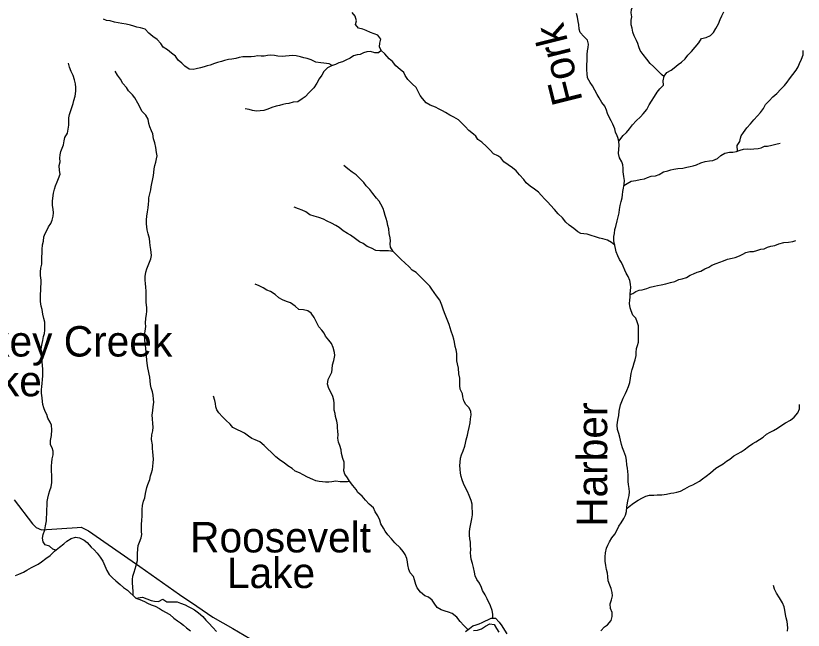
# Model space of a CAD drawing. Extents: x 1624196 to 2029251, y 146837 to 440034.
# Drawn here: x 1772378 to 1785324, y 265741 to 275842 of the extents above; entities that cross this region are included whole.
import ezdxf

# ---------------------------------------------------------------- set-up
doc = ezdxf.new("R2010")
doc.units = 0
for name, color, linetype in [('GM_X_Major_River', 7, 'Continuous'), ('GM_X_Minor_Lake', 7, 'Continuous'), ('GM_X_Minor_Lake_Text', 7, 'Continuous'), ('GM_X_Minor_River', 7, 'Continuous'), ('GM_X_Minor_River_Text', 7, 'Continuous'), ('GM_X_State_Route', 7, 'Continuous')]:
    doc.layers.add(name, color=color, linetype=linetype)

msp = doc.modelspace()

# ---------------------------------------------------------------- linework, layer by layer
at = {"layer": 'GM_X_Major_River'}
for points in [[(1772376, 266640), (1772430, 266662), (1772506, 266698), (1772560, 266728), (1772635, 266773), (1772691, 266799), (1772745, 266829), (1772803, 266865), (1772873, 266920), (1772944, 266972), (1773016, 267040), (1773098, 267107), (1773168, 267163), (1773220, 267207), (1773289, 267250), (1773359, 267270), (1773427, 267262), (1773500, 267222), (1773550, 267184), (1773616, 267106), (1773667, 267062), (1773715, 267006), (1773765, 266944), (1773812, 266876), (1773844, 266800), (1773874, 266725), (1773912, 266657), (1773971, 266601), (1774025, 266551), (1774096, 266493), (1774150, 266443), (1774214, 266397), (1774353, 266269)], [(1779772, 265721), (1779836, 265772), (1779894, 265816), (1779945, 265830), (1779997, 265846), (1780047, 265870), (1780196, 265939)], [(1780196, 265939), (1780264, 265937), (1780324, 265875), (1780371, 265811), (1780415, 265743), (1780451, 265681)], [(1779903, 265736), (1779969, 265742), (1780035, 265764), (1780099, 265810), (1780170, 265845), (1780240, 265837), (1780280, 265769), (1780317, 265710)]]:
    msp.add_lwpolyline(points, dxfattribs=at)
at = {"layer": 'GM_X_Minor_Lake'}
for points in [[(1774353, 266269), (1774462, 266287), (1774530, 266257), (1774604, 266232), (1774659, 266220), (1774727, 266216), (1774793, 266254), (1774859, 266208), (1774910, 266206), (1774980, 266208), (1775034, 266210), (1775088, 266188), (1775163, 266159), (1775213, 266131), (1775265, 266103), (1775316, 266075), (1775380, 266027), (1775454, 265967), (1775501, 265907), (1775551, 265857), (1775615, 265788), (1775676, 265718)], [(1774353, 266269), (1774419, 266247), (1774494, 266213), (1774544, 266187), (1774602, 266157), (1774667, 266135), (1774741, 266097), (1774791, 266065), (1774842, 266040), (1774910, 266000), (1774978, 265940), (1775035, 265896), (1775085, 265862), (1775135, 265822), (1775186, 265779), (1775250, 265729)]]:
    msp.add_lwpolyline(points, dxfattribs=at)
at = {"layer": 'GM_X_Minor_River'}
for points in [[(1783036, 274837), (1782991, 274878), (1782931, 274936), (1782863, 275005), (1782808, 275059), (1782750, 275126), (1782691, 275203), (1782641, 275273), (1782619, 275333), (1782602, 275384), (1782582, 275434), (1782542, 275510), (1782523, 275571), (1782509, 275639), (1782496, 275691), (1782494, 275769), (1782504, 275825), (1782497, 275888), (1782499, 275942), (1782522, 276000), (1782536, 276050)], [(1779939, 273861), (1779901, 273897), (1779827, 273955), (1779768, 274024), (1779712, 274076), (1779654, 274133), (1779582, 274174), (1779512, 274210), (1779443, 274251), (1779391, 274277), (1779337, 274305), (1779277, 274340), (1779191, 274371), (1779127, 274409), (1779066, 274482), (1779028, 274532), (1778995, 274598), (1778959, 274665), (1778893, 274725), (1778826, 274796), (1778782, 274859), (1778756, 274909), (1778695, 274961), (1778625, 275020), (1778571, 275089), (1778518, 275135), (1778444, 275214), (1778386, 275270), (1778355, 275331), (1778361, 275389), (1778382, 275455), (1778330, 275523), (1778210, 275568), (1778140, 275599), (1778084, 275621), (1778010, 275640), (1777963, 275698), (1777977, 275758), (1777958, 275835), (1777908, 275893)], [(1782290, 273781), (1782365, 273873), (1782418, 273923), (1782468, 273983), (1782517, 274050), (1782577, 274112), (1782646, 274178), (1782692, 274232), (1782751, 274300), (1782789, 274376), (1782830, 274440), (1782876, 274513), (1782925, 274583), (1782967, 274641), (1783026, 274701), (1783020, 274773), (1783039, 274847), (1783081, 274907), (1783153, 274945), (1783204, 274987), (1783268, 275040), (1783322, 275080), (1783385, 275136), (1783429, 275192), (1783488, 275254), (1783548, 275327), (1783609, 275397), (1783649, 275467), (1783726, 275483), (1783798, 275516), (1783846, 275568), (1783885, 275634), (1783929, 275708), (1783958, 275778), (1783984, 275838), (1784021, 275908)], [(1777578, 275024), (1777528, 275051), (1777444, 275062), (1777392, 275068), (1777310, 275081), (1777232, 275115), (1777168, 275138), (1777116, 275148), (1777060, 275166), (1776986, 275185), (1776922, 275189), (1776872, 275182), (1776810, 275176), (1776756, 275174), (1776684, 275179), (1776630, 275187), (1776572, 275196), (1776518, 275190), (1776462, 275180), (1776410, 275179), (1776352, 275181), (1776301, 275173), (1776247, 275168), (1776195, 275168), (1776113, 275164), (1776049, 275155), (1775995, 275141), (1775929, 275129), (1775877, 275122), (1775808, 275108), (1775758, 275092), (1775694, 275075), (1775644, 275055), (1775576, 275027), (1775526, 275018), (1775473, 275004), (1775417, 274986), (1775345, 274971), (1775293, 274961), (1775229, 274965), (1775155, 275014), (1775107, 275065), (1775048, 275113), (1775006, 275175), (1774936, 275226), (1774873, 275279), (1774803, 275327), (1774761, 275384), (1774701, 275452), (1774632, 275503), (1774568, 275557), (1774506, 275620), (1774428, 275642), (1774370, 275653), (1774319, 275669), (1774263, 275686), (1774191, 275704), (1774123, 275717), (1774061, 275727), (1773999, 275739), (1773929, 275756), (1773871, 275762), (1773819, 275785)], [(1782277, 273843), (1782263, 273868), (1782240, 273930), (1782226, 273982), (1782192, 274059), (1782167, 274115), (1782139, 274165), (1782107, 274236), (1782088, 274288), (1782062, 274354), (1782011, 274417), (1781971, 274491), (1781937, 274550), (1781900, 274620), (1781858, 274690), (1781819, 274743), (1781775, 274821), (1781771, 274892), (1781766, 274948), (1781768, 275010), (1781769, 275136), (1781774, 275204), (1781778, 275263), (1781786, 275321), (1781795, 275373), (1781777, 275443), (1781717, 275500), (1781658, 275566), (1781640, 275622), (1781635, 275699), (1781625, 275749), (1781613, 275817), (1781598, 275877)], [(1778387, 275269), (1778340, 275234), (1778280, 275235), (1778208, 275253), (1778148, 275250), (1778092, 275232), (1778042, 275206), (1777989, 275197), (1777931, 275183), (1777873, 275145), (1777803, 275110), (1777752, 275086), (1777688, 275066), (1777632, 275042), (1777568, 275021), (1777501, 274983), (1777445, 274923), (1777409, 274865), (1777368, 274803), (1777328, 274733), (1777279, 274658), (1777204, 274580), (1777138, 274510), (1777088, 274474), (1777013, 274427), (1776937, 274423), (1776867, 274402), (1776817, 274394), (1776767, 274384), (1776712, 274366), (1776660, 274353), (1776588, 274331), (1776524, 274305), (1776454, 274286), (1776394, 274280), (1776337, 274275), (1776271, 274283), (1776217, 274299), (1776148, 274312)], [(1784293, 273828), (1784301, 273869), (1784344, 273922), (1784394, 273998), (1784455, 274066), (1784513, 274130), (1784572, 274196), (1784622, 274252), (1784671, 274315), (1784705, 274385), (1784766, 274443), (1784826, 274507), (1784889, 274565), (1784957, 274636), (1785018, 274696), (1785062, 274750), (1785100, 274804), (1785155, 274874), (1785208, 274950), (1785238, 275004), (1785262, 275058), (1785295, 275126), (1785321, 275200), (1785324, 275270)], [(1773230, 273912), (1773242, 273975), (1773252, 274041), (1773249, 274100), (1773249, 274164), (1773262, 274218), (1773276, 274268), (1773298, 274334), (1773321, 274398), (1773333, 274448), (1773352, 274520), (1773366, 274600), (1773367, 274662), (1773359, 274723), (1773346, 274789), (1773322, 274861), (1773288, 274928), (1773261, 274996), (1773247, 275060)], [(1774631, 273901), (1774609, 273951), (1774580, 274017), (1774568, 274073), (1774557, 274143), (1774515, 274210), (1774451, 274274), (1774418, 274343), (1774384, 274407), (1774337, 274494), (1774299, 274544), (1774233, 274607), (1774196, 274663), (1774136, 274728), (1774098, 274802), (1774051, 274867), (1774011, 274933)], [(1773108, 273238), (1773095, 273300), (1773093, 273382), (1773108, 273442), (1773104, 273500), (1773106, 273555), (1773121, 273613), (1773143, 273665), (1773160, 273719), (1773174, 273785), (1773186, 273839), (1773230, 273912)], [(1774544, 272616), (1774552, 272684), (1774561, 272744), (1774563, 272797), (1774567, 272851), (1774582, 272913), (1774596, 272979), (1774604, 273031), (1774617, 273083), (1774627, 273133), (1774642, 273217), (1774648, 273267), (1774655, 273323), (1774665, 273381), (1774683, 273435), (1774694, 273488), (1774700, 273540), (1774694, 273596), (1774681, 273676), (1774663, 273752), (1774642, 273819), (1774631, 273901)], [(1782226, 272073), (1782172, 272116), (1782106, 272152), (1782030, 272175), (1781977, 272187), (1781909, 272206), (1781839, 272232), (1781773, 272250), (1781719, 272259), (1781669, 272265), (1781617, 272291), (1781551, 272344), (1781473, 272398), (1781423, 272451), (1781365, 272521), (1781296, 272586), (1781232, 272655), (1781170, 272727), (1781126, 272777), (1781078, 272828), (1781014, 272892), (1780971, 272943), (1780907, 272991), (1780837, 273038), (1780767, 273096), (1780731, 273151), (1780661, 273225), (1780605, 273292), (1780542, 273344), (1780472, 273389), (1780404, 273443), (1780354, 273504), (1780302, 273538), (1780234, 273570), (1780178, 273631), (1780116, 273693), (1780042, 273762), (1779976, 273807), (1779939, 273861)], [(1782481, 271268), (1782486, 271324), (1782488, 271374), (1782483, 271430), (1782471, 271491), (1782443, 271557), (1782413, 271609), (1782392, 271659), (1782364, 271724), (1782336, 271784), (1782302, 271836), (1782275, 271895), (1782251, 271963), (1782237, 272015), (1782228, 272065), (1782212, 272140), (1782208, 272212), (1782219, 272262), (1782227, 272328), (1782242, 272380), (1782262, 272470), (1782283, 272536), (1782295, 272602), (1782304, 272656), (1782312, 272723), (1782328, 272787), (1782345, 272849), (1782353, 272899), (1782360, 272955), (1782370, 273005), (1782380, 273073), (1782387, 273131), (1782377, 273199), (1782364, 273274), (1782364, 273336), (1782360, 273390), (1782343, 273440), (1782301, 273505), (1782285, 273577), (1782292, 273647), (1782300, 273711), (1782290, 273781), (1782277, 273843)], [(1784243, 273617), (1784237, 273710), (1784279, 273776), (1784293, 273828)], [(1782377, 273049), (1782429, 273087), (1782497, 273125), (1782569, 273134), (1782642, 273152), (1782712, 273161), (1782764, 273183), (1782821, 273203), (1782895, 273212), (1782957, 273232), (1783024, 273274), (1783098, 273294), (1783149, 273309), (1783199, 273321), (1783263, 273329), (1783343, 273336), (1783408, 273352), (1783464, 273364), (1783516, 273375), (1783567, 273391), (1783639, 273423), (1783711, 273444), (1783784, 273456), (1783840, 273460), (1783916, 273495), (1783967, 273547), (1784037, 273581), (1784112, 273599), (1784166, 273602), (1784228, 273612), (1784289, 273634), (1784341, 273647), (1784405, 273653), (1784459, 273649), (1784514, 273652), (1784580, 273662), (1784630, 273672), (1784686, 273698), (1784737, 273699), (1784805, 273713), (1784873, 273729), (1784942, 273750)], [(1778533, 272090), (1778541, 272140), (1778531, 272191), (1778516, 272265), (1778512, 272337), (1778496, 272395), (1778483, 272454), (1778467, 272510), (1778453, 272560), (1778432, 272616), (1778416, 272676), (1778382, 272743), (1778350, 272793), (1778309, 272844), (1778249, 272918), (1778197, 272985), (1778139, 273047), (1778099, 273101), (1778032, 273168), (1777972, 273226), (1777906, 273269), (1777838, 273323), (1777774, 273378)], [(1773039, 267059), (1772988, 267075), (1772932, 267121), (1772864, 267144), (1772826, 267196), (1772816, 267256), (1772827, 267314), (1772855, 267392), (1772868, 267457), (1772882, 267537), (1772886, 267589), (1772891, 267655), (1772891, 267727), (1772894, 267793), (1772894, 267857), (1772905, 267914), (1772921, 267982), (1772937, 268036), (1772958, 268100), (1772970, 268170), (1772973, 268220), (1772969, 268290), (1772968, 268358), (1772968, 268442), (1772970, 268501), (1772979, 268559), (1772991, 268623), (1772992, 268685), (1772976, 268737), (1772948, 268789), (1772951, 268858), (1772965, 268942), (1772972, 269036), (1772964, 269110), (1772942, 269160), (1772905, 269229), (1772887, 269285), (1772863, 269339), (1772840, 269396), (1772822, 269450), (1772820, 269500), (1772810, 269560), (1772801, 269636), (1772799, 269695), (1772804, 269745), (1772814, 269797), (1772816, 269865), (1772823, 269923), (1772825, 269977), (1772823, 270027), (1772816, 270098), (1772810, 270150), (1772808, 270204), (1772805, 270262), (1772801, 270312), (1772797, 270366), (1772812, 270452), (1772824, 270506), (1772833, 270569), (1772849, 270619), (1772858, 270671), (1772858, 270749), (1772854, 270805), (1772837, 270865), (1772823, 270934), (1772814, 271014), (1772796, 271070), (1772784, 271146), (1772783, 271198), (1772787, 271261), (1772789, 271333), (1772792, 271383), (1772794, 271443), (1772796, 271497), (1772787, 271571), (1772785, 271634), (1772792, 271690), (1772804, 271760), (1772809, 271820), (1772810, 272000), (1772820, 272076), (1772833, 272139), (1772841, 272205), (1772859, 272261), (1772888, 272313), (1772916, 272371), (1772953, 272425), (1772979, 272481), (1772994, 272547), (1772996, 272603), (1772992, 272665), (1772983, 272723), (1772983, 272795), (1772986, 272845), (1772998, 272924), (1773013, 272992), (1773029, 273044), (1773059, 273110), (1773080, 273164), (1773108, 273238)], [(1778580, 271968), (1778508, 271978), (1778432, 271975), (1778361, 271975), (1778297, 271983), (1778225, 272020), (1778153, 272048), (1778089, 272097), (1778029, 272125), (1777965, 272174), (1777883, 272234), (1777833, 272261), (1777763, 272309), (1777693, 272360), (1777639, 272394), (1777569, 272431), (1777499, 272467), (1777435, 272500), (1777361, 272526), (1777285, 272547), (1777215, 272569), (1777147, 272620), (1777089, 272648), (1777025, 272668), (1776953, 272695)], [(1774309, 266310), (1774308, 266376), (1774302, 266450), (1774297, 266522), (1774295, 266576), (1774300, 266628), (1774322, 266697), (1774342, 266749), (1774359, 266805), (1774377, 266889), (1774378, 267005), (1774383, 267075), (1774391, 267133), (1774411, 267189), (1774438, 267259), (1774448, 267313), (1774447, 267366), (1774445, 267416), (1774447, 267480), (1774452, 267548), (1774454, 267616), (1774457, 267668), (1774457, 267724), (1774461, 267791), (1774480, 267861), (1774498, 267915), (1774513, 267987), (1774523, 268037), (1774533, 268089), (1774550, 268139), (1774580, 268219), (1774595, 268281), (1774607, 268331), (1774626, 268385), (1774634, 268439), (1774638, 268495), (1774641, 268551), (1774639, 268614), (1774633, 268674), (1774628, 268726), (1774626, 268790), (1774611, 268874), (1774617, 268955), (1774632, 269017), (1774638, 269077), (1774634, 269141), (1774627, 269215), (1774623, 269277), (1774630, 269351), (1774636, 269414), (1774647, 269488), (1774645, 269540), (1774639, 269606), (1774624, 269662), (1774602, 269723), (1774594, 269779), (1774583, 269903), (1774573, 269953), (1774561, 270004), (1774550, 270056), (1774536, 270130), (1774530, 270182), (1774527, 270250), (1774519, 270300), (1774514, 270383), (1774506, 270451), (1774502, 270521), (1774495, 270593), (1774505, 270659), (1774514, 270732), (1774510, 270786), (1774517, 270872), (1774527, 270932), (1774534, 270986), (1774530, 271046), (1774524, 271127), (1774519, 271191), (1774519, 271241), (1774524, 271313), (1774518, 271381), (1774512, 271439), (1774507, 271496), (1774507, 271558), (1774515, 271626), (1774532, 271680), (1774552, 271734), (1774577, 271792), (1774599, 271848), (1774607, 271900), (1774606, 271952), (1774600, 272002), (1774590, 272065), (1774581, 272121), (1774577, 272181), (1774554, 272259), (1774540, 272321), (1774532, 272372), (1774528, 272424), (1774525, 272486), (1774531, 272546), (1774544, 272616)], [(1782481, 271260), (1782520, 271276), (1782574, 271310), (1782624, 271329), (1782677, 271337), (1782753, 271361), (1782805, 271380), (1782878, 271398), (1782930, 271410), (1782986, 271419), (1783063, 271433), (1783141, 271457), (1783215, 271472), (1783276, 271504), (1783334, 271520), (1783404, 271537), (1783467, 271575), (1783519, 271601), (1783582, 271629), (1783640, 271644), (1783704, 271682), (1783769, 271710), (1783819, 271740), (1783894, 271771), (1783954, 271791), (1784014, 271813), (1784079, 271838), (1784153, 271856), (1784203, 271866), (1784278, 271893), (1784330, 271925), (1784380, 271951), (1784443, 271967), (1784505, 271968), (1784559, 271982), (1784628, 272004), (1784680, 272011), (1784738, 272037), (1784789, 272057), (1784859, 272064), (1784925, 272094), (1785002, 272112), (1785080, 272119), (1785150, 272129), (1785201, 272145)], [(1780224, 265938), (1780220, 265943), (1780219, 266004), (1780209, 266066), (1780181, 266142), (1780130, 266255), (1780092, 266325), (1780051, 266396), (1780033, 266446), (1780001, 266514), (1779955, 266577), (1779932, 266635), (1779922, 266695), (1779904, 266771), (1779885, 266838), (1779865, 266908), (1779857, 266958), (1779852, 267014), (1779858, 267068), (1779854, 267136), (1779851, 267187), (1779845, 267243), (1779839, 267305), (1779838, 267359), (1779842, 267409), (1779852, 267461), (1779865, 267515), (1779875, 267573), (1779884, 267640), (1779884, 267692), (1779882, 267746), (1779879, 267814), (1779865, 267872), (1779831, 267955), (1779806, 268021), (1779764, 268093), (1779738, 268154), (1779719, 268212), (1779701, 268270), (1779691, 268322), (1779682, 268387), (1779680, 268449), (1779682, 268501), (1779691, 268569), (1779703, 268625), (1779734, 268691), (1779758, 268765), (1779769, 268817), (1779783, 268869), (1779804, 268949), (1779816, 269003), (1779830, 269073), (1779847, 269148), (1779855, 269214), (1779864, 269284), (1779860, 269338), (1779834, 269396), (1779775, 269453), (1779745, 269511), (1779729, 269575), (1779720, 269629), (1779684, 269704), (1779678, 269762), (1779679, 269818), (1779677, 269882), (1779663, 269957), (1779656, 270051), (1779640, 270119), (1779631, 270169), (1779629, 270226), (1779627, 270290), (1779620, 270348), (1779604, 270404), (1779588, 270474), (1779579, 270527), (1779563, 270581), (1779535, 270659), (1779518, 270713), (1779502, 270766), (1779482, 270824), (1779446, 270906), (1779425, 270958), (1779405, 271021), (1779381, 271085), (1779348, 271165), (1779296, 271236), (1779256, 271292), (1779218, 271345), (1779187, 271395), (1779133, 271451), (1779081, 271500), (1779033, 271552), (1778961, 271619), (1778895, 271661), (1778843, 271712), (1778772, 271782), (1778714, 271835), (1778648, 271899), (1778580, 271968), (1778536, 272038), (1778533, 272090)], [(1776379, 271403), (1776315, 271431)], [(1779814, 265754), (1779806, 265759), (1779746, 265818), (1779684, 265886), (1779630, 265955), (1779552, 266015), (1779494, 266038), (1779438, 266056), (1779370, 266077), (1779306, 266117), (1779254, 266184), (1779223, 266236), (1779161, 266286), (1779103, 266309), (1779031, 266365), (1778977, 266438), (1778955, 266494), (1778932, 266570), (1778916, 266623), (1778862, 266685), (1778840, 266737), (1778821, 266814), (1778817, 266864), (1778805, 266918), (1778778, 266986), (1778746, 267037), (1778700, 267097), (1778610, 267176), (1778557, 267242), (1778493, 267307), (1778453, 267367), (1778421, 267417), (1778377, 267490), (1778362, 267550), (1778328, 267620), (1778286, 267685), (1778257, 267755), (1778187, 267814), (1778129, 267880), (1778071, 267943), (1778001, 268003), (1777974, 268055), (1777918, 268120), (1777862, 268194), (1777830, 268245), (1777788, 268305), (1777773, 268361), (1777777, 268431), (1777778, 268504), (1777754, 268566), (1777732, 268646), (1777725, 268704), (1777707, 268777), (1777685, 268833), (1777672, 268899), (1777676, 268953), (1777674, 269016), (1777667, 269070), (1777665, 269120), (1777657, 269178), (1777636, 269252), (1777630, 269306), (1777614, 269361), (1777611, 269413), (1777611, 269471), (1777605, 269523), (1777590, 269583), (1777556, 269654), (1777526, 269712), (1777501, 269784), (1777513, 269861), (1777544, 269931), (1777572, 269983), (1777582, 270033), (1777585, 270101), (1777605, 270175), (1777622, 270255), (1777620, 270309), (1777595, 270391), (1777569, 270456), (1777525, 270508), (1777469, 270575), (1777448, 270625), (1777412, 270675), (1777360, 270730), (1777324, 270804), (1777285, 270882), (1777233, 270951), (1777177, 270989), (1777109, 271006), (1777033, 271012), (1776969, 271067), (1776895, 271121), (1776827, 271144), (1776761, 271174), (1776703, 271204), (1776641, 271259), (1776563, 271308), (1776503, 271332), (1776445, 271368), (1776379, 271403)], [(1781995, 265731), (1782054, 265797), (1782108, 265832), (1782165, 265900), (1782183, 265968), (1782180, 266033), (1782154, 266099), (1782151, 266173), (1782173, 266241), (1782186, 266307), (1782182, 266361), (1782166, 266426), (1782142, 266480), (1782119, 266554), (1782111, 266624), (1782104, 266677), (1782090, 266737), (1782078, 266807), (1782065, 266877), (1782065, 266950), (1782074, 267012), (1782090, 267088), (1782110, 267138), (1782137, 267194), (1782177, 267262), (1782226, 267322), (1782267, 267391), (1782291, 267449), (1782330, 267509), (1782376, 267579), (1782403, 267631), (1782417, 267695), (1782423, 267764), (1782434, 267836), (1782448, 267888), (1782463, 267956), (1782467, 268018), (1782462, 268072), (1782450, 268134), (1782446, 268184), (1782445, 268245), (1782445, 268297), (1782441, 268353), (1782436, 268405), (1782426, 268461), (1782416, 268537), (1782407, 268596), (1782375, 268682), (1782353, 268742), (1782334, 268793), (1782320, 268865), (1782308, 268915), (1782291, 268973), (1782269, 269042), (1782267, 269112), (1782272, 269162), (1782280, 269220), (1782290, 269272), (1782299, 269344), (1782320, 269448), (1782342, 269500), (1782364, 269558), (1782399, 269630), (1782423, 269684), (1782452, 269750), (1782472, 269812), (1782485, 269884), (1782495, 269959), (1782510, 270025), (1782526, 270077), (1782543, 270135), (1782561, 270185), (1782576, 270259), (1782578, 270309), (1782584, 270373), (1782597, 270423), (1782615, 270479), (1782613, 270537), (1782614, 270612), (1782618, 270668), (1782613, 270746), (1782595, 270810), (1782569, 270870), (1782525, 270921), (1782494, 270989), (1782476, 271039), (1782470, 271110), (1782475, 271164), (1782481, 271214), (1782481, 271268)], [(1777870, 268184), (1777832, 268183), (1777762, 268181), (1777709, 268183), (1777639, 268190), (1777573, 268182), (1777523, 268174), (1777468, 268177), (1777418, 268183), (1777364, 268187), (1777312, 268196), (1777260, 268218), (1777172, 268256), (1777102, 268293), (1777042, 268327), (1776972, 268358), (1776920, 268398), (1776848, 268443), (1776790, 268491), (1776730, 268530), (1776656, 268594), (1776582, 268663), (1776516, 268721), (1776463, 268780), (1776391, 268840), (1776311, 268873), (1776259, 268895), (1776205, 268932), (1776137, 268980), (1776085, 269010), (1776021, 269035), (1775949, 269071), (1775901, 269126), (1775833, 269194), (1775775, 269247), (1775717, 269315), (1775684, 269366), (1775666, 269416), (1775660, 269466), (1775652, 269516), (1775627, 269588)], [(1782422, 267744), (1782462, 267773), (1782534, 267829), (1782609, 267879), (1782679, 267920), (1782734, 267946), (1782796, 267960), (1782866, 267964), (1782923, 267967), (1783001, 267967), (1783077, 267978), (1783147, 267994), (1783198, 268000), (1783248, 268011), (1783304, 268029), (1783377, 268065), (1783453, 268109), (1783508, 268130), (1783560, 268158), (1783616, 268194), (1783669, 268228), (1783729, 268271), (1783800, 268331), (1783889, 268403), (1783941, 268437), (1784010, 268478), (1784060, 268522), (1784116, 268554), (1784181, 268610), (1784241, 268641), (1784302, 268671), (1784354, 268705), (1784425, 268763), (1784493, 268808), (1784544, 268838), (1784604, 268876), (1784663, 268912), (1784719, 268964), (1784782, 268999), (1784834, 269023), (1784898, 269061), (1784957, 269102), (1785033, 269152), (1785114, 269194), (1785174, 269242), (1785235, 269317), (1785262, 269383), (1785264, 269454)], [(1785066, 265725), (1785070, 265778), (1785059, 265886), (1785045, 265946), (1785030, 266000), (1785020, 266069), (1785008, 266125), (1784983, 266191), (1784935, 266272), (1784883, 266350), (1784852, 266418), (1784836, 266475)]]:
    msp.add_lwpolyline(points, dxfattribs=at)
at = {"layer": 'GM_X_State_Route'}
msp.add_lwpolyline([(1772350, 267884), (1772653, 267491), (1772715, 267432), (1772801, 267391), (1773385, 267428), (1773454, 267434), (1773574, 267375), (1774417, 266790), (1775069, 266328), (1775356, 266136), (1775620, 265956), (1775944, 265771), (1776228, 265605)], dxfattribs=at)

# ---------------------------------------------------------------- texts
at = {"layer": 'GM_X_Minor_Lake_Text'}
for s, height, rotation, p in [('Turkey Creek', 500.01, 0.0044, (1770938, 270240)), ('Lake', 500, 0.0045, (1771358, 269586)), ('Roosevelt', 500, 0.0024, (1775245, 267020)), ('Lake', 500, 0.0025, (1775849, 266434))]:
    msp.add_text(s, height=height, rotation=rotation, dxfattribs=at).set_placement(p)
at = {"layer": 'GM_X_Minor_River_Text'}
for s, rotation, p in [('Fork', 104.0019, (1781700, 274448)), ('Harber', 90.0024, (1782101, 267441))]:
    msp.add_text(s, height=500, rotation=rotation, dxfattribs=at).set_placement(p)

doc.saveas('drawing.dxf')
